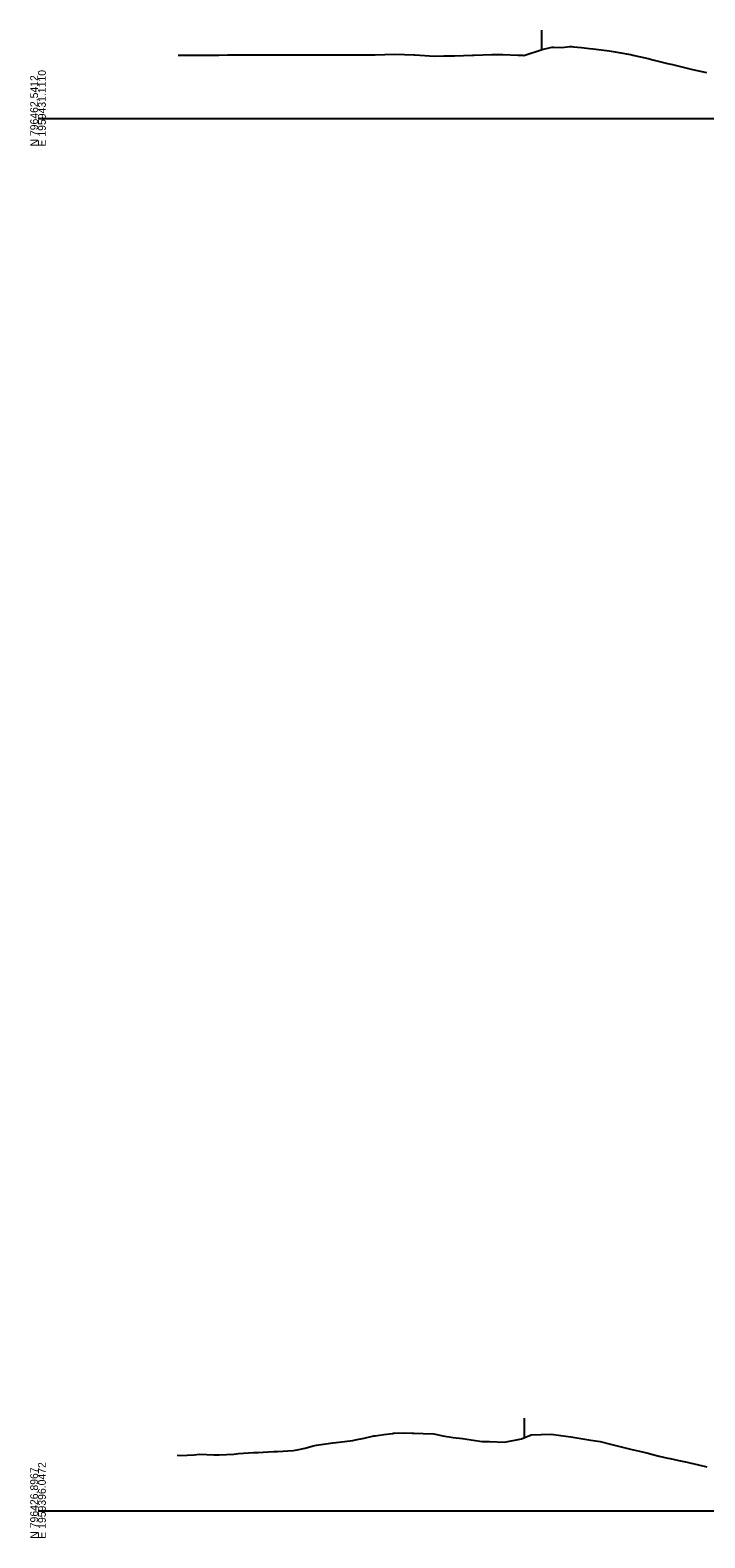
# Model space of a CAD drawing. Extents: x -4026 to 9638, y -10 to 19609.
# Drawn here: x -1003 to -760, y 990 to 1532 of the extents above; entities that cross this region are included whole.
import ezdxf

# ---------------------------------------------------------------- set-up
doc = ezdxf.new("R2010")
doc.units = 0
for name, color, linetype in [('Default', 7, 'Continuous'), ('RD_EX_Fence_Other', 7, 'Continuous'), ('RD_GPK_XS_Cell', 7, 'Continuous'), ('RD_XS_ExGround', 7, 'Continuous')]:
    doc.layers.add(name, color=color, linetype=linetype)

msp = doc.modelspace()

# ---------------------------------------------------------------- linework, layer by layer
at = {"layer": 'RD_EX_Fence_Other'}
for p, q in [((-819.05, 1531.79), (-819.05, 1524.79)), ((-825.24, 1033.29), (-825.24, 1026.29))]:
    msp.add_line(p, q, dxfattribs=at)
at = {"layer": 'RD_GPK_XS_Cell'}
for p, q in [((-1000, 1500), (-650, 1500)), ((-1000, 1000), (-650, 1000))]:
    msp.add_line(p, q, dxfattribs=at)
at = {"layer": 'RD_XS_ExGround'}
for points in [[(-949.56, 1522.83), (-949.03, 1522.83), (-942.97, 1522.84), (-942.01, 1522.84), (-935.84, 1522.86), (-935, 1522.86), (-931.88, 1522.87), (-928.71, 1522.87), (-928.35, 1522.87), (-927.98, 1522.87), (-924.81, 1522.88), (-921.58, 1522.89), (-921.28, 1522.89), (-920.97, 1522.89), (-913.96, 1522.9), (-910.67, 1522.91), (-906.94, 1522.92), (-899.93, 1522.93), (-896.53, 1522.94), (-892.92, 1522.95), (-889.45, 1522.96), (-885.9, 1522.96), (-883.94, 1522.95), (-878.81, 1522.94), (-875.31, 1523.01), (-871.68, 1523.13), (-868.24, 1523.1), (-864.86, 1522.91), (-864.55, 1522.88), (-857.42, 1522.45), (-854.1, 1522.52), (-850.29, 1522.59), (-847.03, 1522.69), (-843.82, 1522.81), (-843.49, 1522.82), (-843.16, 1522.83), (-836.81, 1522.99), (-836.42, 1523), (-836.03, 1523), (-832.88, 1523.03), (-827.49, 1522.79), (-825.7, 1522.75), (-825.33, 1522.74), (-818.74, 1524.89), (-815.77, 1525.51), (-815.21, 1525.66), (-814.64, 1525.64), (-811.67, 1525.61), (-808.75, 1525.86), (-808.13, 1525.91), (-807.51, 1525.85), (-804.6, 1525.55), (-801.74, 1525.25), (-800.38, 1525.08), (-794.72, 1524.33), (-793.99, 1524.26), (-793.25, 1524.15), (-790.46, 1523.68), (-787.71, 1523.14), (-786.92, 1523.01), (-786.12, 1522.82), (-780.7, 1521.58), (-779.85, 1521.39), (-778.99, 1521.18), (-773.68, 1519.82), (-771.86, 1519.41), (-766.67, 1518.18), (-765.71, 1517.94), (-764.73, 1517.69), (-759.66, 1516.58)], [(-949.97, 1020.02), (-948.94, 1019.93), (-943.89, 1020.11), (-941.92, 1020.33), (-936.76, 1020.16), (-934.91, 1020.17), (-929.63, 1020.36), (-927.9, 1020.55), (-922.5, 1021.01), (-920.88, 1020.97), (-915.37, 1021.28), (-913.87, 1021.33), (-908.24, 1021.64), (-906.85, 1021.91), (-904.01, 1022.55), (-901.11, 1023.35), (-899.84, 1023.54), (-893.98, 1024.4), (-892.83, 1024.55), (-886.85, 1025.3), (-885.81, 1025.5), (-882.79, 1026.14), (-879.72, 1026.79), (-879.26, 1026.9), (-878.8, 1026.97), (-875.72, 1027.38), (-872.59, 1027.83), (-872.19, 1027.87), (-871.79, 1027.89), (-868.65, 1028.03), (-865.46, 1027.9), (-864.77, 1027.86), (-861.58, 1027.75), (-857.76, 1027.72), (-854.51, 1027), (-850.74, 1026.38), (-847.44, 1025.96), (-841.18, 1025.07), (-840.28, 1024.96), (-837.69, 1024.93), (-832.35, 1024.67), (-826.22, 1025.88), (-822.69, 1027.36), (-815.56, 1027.54), (-812.08, 1027.06), (-808.43, 1026.59), (-801.3, 1025.36), (-797.94, 1024.85), (-794.17, 1023.95), (-787.04, 1022.12), (-783.8, 1021.4), (-780.61, 1020.7), (-780.26, 1020.62), (-779.91, 1020.52), (-776.72, 1019.62), (-773.59, 1018.93), (-772.78, 1018.75), (-769.65, 1018.06), (-766.58, 1017.45), (-766.12, 1017.34), (-765.65, 1017.24), (-762.58, 1016.48), (-759.57, 1015.82)]]:
    msp.add_lwpolyline(points, dxfattribs=at)

# ---------------------------------------------------------------- texts
at = {"layer": 'Default'}
for p in [(-1000, 1500), (-1000, 1000)]:
    msp.add_text('-', height=0.0001, dxfattribs=at).set_placement(p)
at = {"layer": 'RD_GPK_XS_Cell'}
for s, p in [('E 1959431.1110', (-997.2, 1490)), ('N 796462.5412', (-1000, 1490)), ('N 796426.8967', (-1000, 990)), ('E 1959396.0472', (-997.2, 990))]:
    msp.add_text(s, height=2.8, rotation=90, dxfattribs=at).set_placement(p)

doc.saveas('drawing.dxf')
